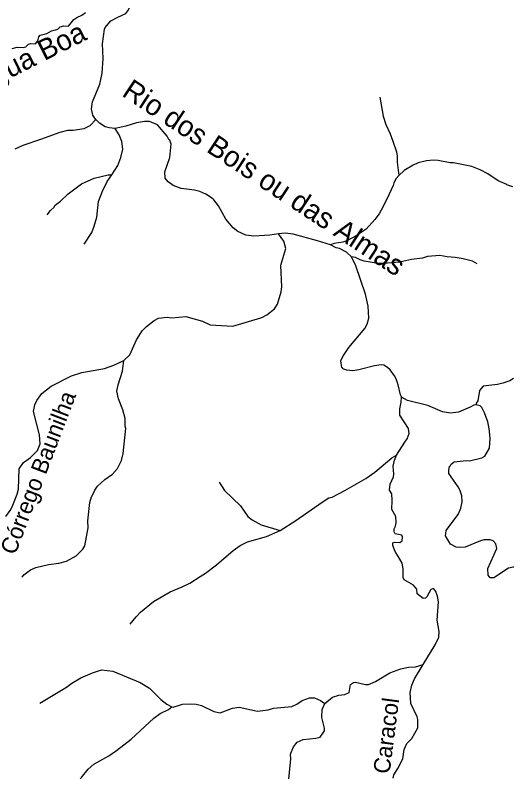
# Model space of a CAD drawing. Extents: x 393 to 446.6, y 8175.5 to 8231.
# Drawn here: x 441.69 to 446.52, y 8219.64 to 8226.96 of the extents above; entities that cross this region are included whole.
import ezdxf
from ezdxf.enums import TextEntityAlignment as Align

# ---------------------------------------------------------------- set-up
doc = ezdxf.new("R2010")
doc.units = 0
doc.header["$LTSCALE"] = 0.064
doc.linetypes.add('LONG_DASHED', pattern=[7.5, 6, -1.5])
doc.layers.add('61', color=7, linetype='Continuous')
doc.layers.add('7', color=7, linetype='Continuous', lineweight=25)
doc.layers.add('9', color=7, linetype='LONG_DASHED', lineweight=25)

msp = doc.modelspace()

# ---------------------------------------------------------------- linework, layer by layer
at = {"layer": '7'}
for points in [[(442.4748, 8225.951), (442.4707, 8225.955), (442.4462, 8225.9931), (442.4316, 8226.0561), (442.4429, 8226.1239), (442.5124, 8226.2951), (442.535, 8226.4017), (442.5463, 8226.5438), (442.5398, 8226.6859), (442.5592, 8226.828), (442.5657, 8226.8441), (442.6205, 8226.907), (442.6868, 8226.9442), (442.7643, 8226.9781), (442.7853, 8227.004), (442.8047, 8227.0411), (442.8047, 8227.054), (442.782, 8227.1267), (442.7078, 8227.2139), (442.5988, 8227.3203)], [(441.6646, 8226.639), (441.7131, 8226.6535), (441.7712, 8226.6487), (441.797, 8226.6551), (441.8228, 8226.681), (441.8455, 8226.6891), (441.8891, 8226.6858), (441.9116, 8226.7133), (441.9213, 8226.7537), (441.9343, 8226.7682), (442.0005, 8226.7843), (442.0457, 8226.8102), (442.0707, 8226.8174), (442.1071, 8226.8279), (442.1281, 8226.8489), (442.1652, 8226.8586), (442.2104, 8226.8554), (442.2605, 8226.9216), (442.2895, 8226.941), (442.3396, 8226.9619), (442.3751, 8226.9878)], [(445.2253, 8226.1685), (445.2591, 8225.985), (445.285, 8225.9027), (445.3254, 8225.8139), (445.3503, 8225.7424), (445.3867, 8225.6378), (445.3948, 8225.5975), (445.3948, 8225.5394), (445.4079, 8225.4097)], [(441.6923, 8225.6685), (441.7696, 8225.7024), (441.9395, 8225.7629), (442.1281, 8225.83), (442.204, 8225.8477), (442.2556, 8225.8477), (442.3622, 8225.8655), (442.4204, 8225.893), (442.4748, 8225.951)], [(442.6606, 8225.8657), (442.6044, 8225.872), (442.5657, 8225.8817), (442.5091, 8225.9172), (442.4748, 8225.951)], [(444.2444, 8224.8438), (444.1611, 8224.832), (444.0061, 8224.8224), (443.9286, 8224.8337), (443.8511, 8224.8692), (443.8058, 8224.9047), (443.7348, 8224.9871), (443.6621, 8225.1163), (443.6169, 8225.1744), (443.5943, 8225.1937), (443.5394, 8225.2309), (443.4829, 8225.2551), (443.4312, 8225.268), (443.302, 8225.2858), (443.2245, 8225.3133), (443.1744, 8225.3504), (443.147, 8225.3827), (443.1438, 8225.4441), (443.1922, 8225.5846), (443.2051, 8225.7138), (443.1922, 8225.7509), (443.1857, 8225.7525), (443.1648, 8225.7913), (443.0727, 8225.8994), (442.9936, 8225.9317), (442.9468, 8225.9317), (442.8693, 8225.9188), (442.7659, 8225.8881), (442.6606, 8225.8657)], [(442.6275, 8225.4182), (442.6867, 8225.5071), (442.7174, 8225.5846), (442.7368, 8225.6653), (442.7255, 8225.7396), (442.6997, 8225.8042), (442.6606, 8225.8657)], [(446.5151, 8225.3016), (446.4561, 8225.3202), (446.4557, 8225.3246), (446.3734, 8225.3585), (446.2732, 8225.4263), (446.199, 8225.4666), (446.1182, 8225.4973), (445.9406, 8225.5312), (445.9083, 8225.5312), (445.792, 8225.5538), (445.7436, 8225.5571), (445.679, 8225.5506), (445.5983, 8225.5312), (445.5498, 8225.5102), (445.4626, 8225.4586), (445.4079, 8225.4097)], [(442.0024, 8225.0309), (442.0344, 8225.0727), (442.0699, 8225.1033), (442.078, 8225.1195), (442.0974, 8225.1372), (442.1313, 8225.1615), (442.2055, 8225.2325), (442.3348, 8225.3294), (442.4591, 8225.3827), (442.5947, 8225.4182), (442.6275, 8225.4182)], [(442.3604, 8224.7441), (442.4365, 8224.8579), (442.4591, 8224.9193), (442.4849, 8225.0065), (442.5011, 8225.1583), (442.5382, 8225.2584), (442.5834, 8225.352), (442.6275, 8225.4182)], [(445.4079, 8225.4097), (445.3851, 8225.3811), (445.3608, 8225.3391), (445.356, 8225.3133), (445.293, 8225.1809), (445.2378, 8225.0753), (445.2187, 8225.0388), (445.1784, 8224.9855), (445.0928, 8224.8918), (444.9975, 8224.8256), (444.9071, 8224.7787), (444.8684, 8224.7658), (444.7844, 8224.7529), (444.749, 8224.7394)], [(444.749, 8224.7394), (444.6226, 8224.7767), (444.3872, 8224.8434), (444.3097, 8224.853), (444.2444, 8224.8438)], [(444.9522, 8224.6239), (444.9023, 8224.6674), (444.836, 8224.7029), (444.8038, 8224.7109), (444.749, 8224.7394)], [(445.4349, 8223.2667), (445.4254, 8223.2878), (445.4045, 8223.382), (445.3851, 8223.4401), (445.369, 8223.4692), (445.327, 8223.5273), (445.3011, 8223.5515), (445.264, 8223.5741), (445.2398, 8223.5774), (445.1752, 8223.5677), (445.0234, 8223.5273), (444.9653, 8223.5192), (444.9071, 8223.5241), (444.8683, 8223.537), (444.8651, 8223.5467), (444.857, 8223.5499), (444.849, 8223.6145), (444.8667, 8223.6565), (444.9249, 8223.7437), (445.0815, 8223.9294), (445.1025, 8223.9698), (445.1186, 8224.0279), (445.1138, 8224.1442), (445.088, 8224.2604), (444.9943, 8224.535), (444.9522, 8224.6239)], [(446.1679, 8224.556), (446.123, 8224.5801), (446.0343, 8224.6043), (445.9567, 8224.6173), (445.8792, 8224.6221), (445.8082, 8224.6366), (445.6887, 8224.627), (445.6386, 8224.6108), (445.5337, 8224.5979), (445.4158, 8224.572), (445.2624, 8224.5591), (445.2107, 8224.5591), (445.0751, 8224.5801), (445.0363, 8224.593), (444.9911, 8224.6173), (444.9522, 8224.6239)], [(446.5196, 8223.444), (446.4841, 8223.4215), (446.4186, 8223.3997), (446.3669, 8223.3868), (446.2264, 8223.3707), (446.1925, 8223.3287), (446.1764, 8223.227), (446.1602, 8223.2043), (446.1577, 8223.1903)], [(446.1577, 8223.1903), (446.1345, 8223.1868), (446.102, 8223.1672), (445.989, 8223.1188), (445.9115, 8223.1074), (445.834, 8223.122), (445.6919, 8223.1833), (445.4949, 8223.2318), (445.4359, 8223.2645), (445.4349, 8223.2667)], [(446.524, 8221.6194), (446.5168, 8221.6177), (446.4734, 8221.6073), (446.3314, 8221.5152), (446.2958, 8221.5136), (446.2765, 8221.5411), (446.2732, 8221.6057), (446.3604, 8221.7995), (446.3507, 8221.8431), (446.3249, 8221.8721), (446.2959, 8221.8818), (446.2345, 8221.8818), (446.2022, 8221.8738), (446.0536, 8221.8108), (445.9955, 8221.8075), (445.9664, 8221.8124), (445.9115, 8221.8414), (445.8631, 8221.9206), (445.8695, 8221.9739), (445.9826, 8222.1257), (445.9864, 8222.1342), (446.0116, 8222.1903), (446.0246, 8222.2516), (446.0213, 8222.3098), (446.0003, 8222.3679), (445.9858, 8222.397), (445.8953, 8222.5261), (445.8937, 8222.5552), (445.9018, 8222.5972), (445.9067, 8222.5972), (445.9164, 8222.6166), (445.947, 8222.6375), (446.0633, 8222.6521), (446.0956, 8222.6488), (446.2151, 8222.6763), (446.2441, 8222.6924), (446.2894, 8222.7716), (446.2958, 8222.8653), (446.2862, 8222.9621), (446.2716, 8223.0235), (446.2409, 8223.1107), (446.2136, 8223.1636), (446.1962, 8223.181), (446.1577, 8223.1903)]]:
    msp.add_lwpolyline(points, dxfattribs=at)
at = {"layer": '9'}
for points in [[(442.7461, 8223.6185), (442.8032, 8223.6751), (442.868, 8223.8203), (442.9229, 8223.9057), (442.9641, 8223.9484), (443.0384, 8224.0064), (443.0802, 8224.0275), (443.1654, 8224.0375), (443.2111, 8224.0327), (443.345, 8224.0458), (443.5062, 8224.0006), (443.5804, 8223.9648), (443.801, 8223.9506), (444.0716, 8224.0323), (444.0823, 8224.0355), (444.1304, 8224.0596), (444.2038, 8224.1206), (444.2348, 8224.1632), (444.2709, 8224.2835), (444.2757, 8224.3309), (444.2661, 8224.5379), (444.266, 8224.5407), (444.3142, 8224.7045), (444.2966, 8224.7754), (444.2444, 8224.8438)], [(441.6005, 8222.1073), (441.6438, 8222.1672), (441.6591, 8222.1965), (441.671, 8222.2192), (441.7121, 8222.3234), (441.7241, 8222.3737), (441.7298, 8222.5705), (441.7741, 8222.6321), (441.8397, 8222.6788), (441.9078, 8222.7474), (441.9341, 8222.8128), (441.9275, 8222.8982), (441.8699, 8223.1252), (441.8828, 8223.1888), (441.9013, 8223.232), (441.951, 8223.3), (442.0398, 8223.3693), (442.2394, 8223.4707), (442.3387, 8223.5012), (442.5595, 8223.542), (442.6489, 8223.5729), (442.7461, 8223.6185)], [(441.76, 8221.5204), (441.7776, 8221.5436), (441.8403, 8221.5928), (441.8933, 8221.615), (442.0148, 8221.6439), (442.116, 8221.6576), (442.1895, 8221.677), (442.2845, 8221.7266), (442.3484, 8221.7919), (442.3684, 8221.8249), (442.4007, 8221.9984), (442.3979, 8222.0679), (442.4172, 8222.2436), (442.4329, 8222.2991), (442.4348, 8222.3032), (442.4632, 8222.3635), (442.4897, 8222.4017), (442.5624, 8222.4676), (442.6345, 8222.5177), (442.6854, 8222.5719), (442.7238, 8222.652), (442.7392, 8222.7192), (442.7641, 8222.962), (442.7578, 8222.984), (442.7576, 8223.0589), (442.7353, 8223.1408), (442.693, 8223.2468), (442.6785, 8223.3222), (442.6899, 8223.3818), (442.7315, 8223.5167), (442.7461, 8223.6185)], [(445.3884, 8222.7027), (445.4688, 8222.8289), (445.4892, 8222.8609), (445.5107, 8222.9116), (445.504, 8222.9612), (445.4192, 8223.0898), (445.4192, 8223.1525), (445.4332, 8223.2166), (445.4349, 8223.2667)], [(444.261, 8221.9734), (444.4129, 8222.0693), (444.6654, 8222.2486), (444.7328, 8222.2878), (444.7641, 8222.2972), (444.8865, 8222.3591), (445.0894, 8222.4765), (445.1774, 8222.5363), (445.3419, 8222.6764), (445.3884, 8222.7027)], [(445.6459, 8220.6753), (445.7612, 8220.866), (445.7967, 8220.9389), (445.8015, 8220.9965), (445.7823, 8221.1036), (445.7951, 8221.2811), (445.7855, 8221.3376), (445.768, 8221.3822), (445.7476, 8221.407), (445.7354, 8221.409), (445.7189, 8221.4006), (445.6822, 8221.3306), (445.6674, 8221.3172), (445.6436, 8221.314), (445.5876, 8221.3611), (445.5837, 8221.4062), (445.5529, 8221.4433), (445.4599, 8221.4944), (445.4523, 8221.5187), (445.4511, 8221.6005), (445.4427, 8221.6559), (445.4053, 8221.7189), (445.3786, 8221.7639), (445.3683, 8221.7871), (445.3498, 8221.8285), (445.3519, 8221.8544), (445.369, 8221.8592), (445.4196, 8221.8551), (445.442, 8221.8744), (445.4456, 8221.9128), (445.4376, 8221.9274), (445.3734, 8221.9404), (445.3639, 8221.9614), (445.3637, 8221.9899), (445.3778, 8222.0135), (445.3848, 8222.0474), (445.3813, 8222.1086), (445.3402, 8222.1768), (445.3463, 8222.2652), (445.3414, 8222.3281), (445.3195, 8222.3639), (445.3253, 8222.4207), (445.359, 8222.493), (445.3623, 8222.5179), (445.353, 8222.5964), (445.3673, 8222.6552), (445.3884, 8222.7027)], [(443.6681, 8222.4397), (443.7197, 8222.3601), (443.8748, 8222.2116), (443.9453, 8222.1082), (443.9891, 8222.0751), (444.0766, 8222.0275), (444.261, 8221.9734)], [(442.8074, 8221.0646), (442.864, 8221.1385), (442.9064, 8221.1808), (443.0332, 8221.2856), (443.1947, 8221.3806), (443.3103, 8221.4267), (443.3836, 8221.4642), (443.4834, 8221.5267), (443.5355, 8221.5594), (443.6435, 8221.6406), (443.8047, 8221.7792), (443.8722, 8221.8269), (443.9434, 8221.8617), (444.1275, 8221.9137), (444.261, 8221.9734)], [(441.9299, 8220.3017), (442.1901, 8220.455), (442.2426, 8220.4945), (442.3285, 8220.5448), (442.4404, 8220.5953), (442.5273, 8220.6252), (442.6402, 8220.6122), (442.9047, 8220.5026), (442.9932, 8220.4464), (443.1046, 8220.3352), (443.1617, 8220.291), (443.21, 8220.2643)], [(444.6924, 8220.2972), (444.6928, 8220.2969), (444.7679, 8220.3603), (444.8287, 8220.3796), (444.885, 8220.3851), (444.9271, 8220.404), (444.9428, 8220.4812), (444.9692, 8220.5027), (444.9884, 8220.5058), (445.0879, 8220.4803), (445.1168, 8220.4804), (445.1827, 8220.5107), (445.3237, 8220.5961), (445.429, 8220.6322), (445.5026, 8220.6486), (445.5723, 8220.6536), (445.6459, 8220.6753)], [(445.3559, 8219.5741), (445.3612, 8219.6064), (445.4013, 8219.6682), (445.4479, 8219.7633), (445.4596, 8219.8526), (445.4861, 8219.9102), (445.5366, 8219.9585), (445.5932, 8220.0612), (445.5935, 8220.142), (445.5865, 8220.169), (445.5257, 8220.2992), (445.518, 8220.4046), (445.5352, 8220.4753), (445.5611, 8220.5351), (445.6459, 8220.6753)], [(443.21, 8220.2643), (443.2238, 8220.2628), (443.3123, 8220.2912), (443.3956, 8220.296), (443.4473, 8220.2911), (443.4977, 8220.2769), (443.6157, 8220.2191), (443.6777, 8220.2075), (443.7994, 8220.2524), (443.8637, 8220.2621), (444.0409, 8220.2236), (444.1437, 8220.2377), (444.194, 8220.254), (444.3735, 8220.2685), (444.4217, 8220.2901), (444.4742, 8220.3266), (444.5434, 8220.3525), (444.5797, 8220.3519), (444.594, 8220.3517), (444.6493, 8220.328), (444.6924, 8220.2972)], [(442.195, 8219.2404), (442.3038, 8219.5252), (442.3331, 8219.5774), (442.3997, 8219.6635), (442.4531, 8219.7117), (442.6, 8219.79), (442.6746, 8219.8412), (442.8161, 8219.9539), (443.036, 8220.1562), (443.0975, 8220.1999), (443.1775, 8220.2402), (443.21, 8220.2643)], [(444.0027, 8219.2705), (444.0095, 8219.3125), (444.0473, 8219.353), (444.1124, 8219.3623), (444.1514, 8219.3466), (444.1961, 8219.345), (444.2089, 8219.3562), (444.2486, 8219.3623), (444.3081, 8219.4393), (444.3263, 8219.4789), (444.3418, 8219.5355), (444.3626, 8219.7583), (444.3613, 8219.807), (444.3887, 8219.8776), (444.4244, 8219.9229), (444.4833, 8219.9489), (444.6054, 8219.9616), (444.6483, 8219.9717), (444.6892, 8220.0323), (444.6898, 8220.0597), (444.6631, 8220.1635), (444.6678, 8220.2401), (444.6924, 8220.2971), (444.6924, 8220.2972)]]:
    msp.add_lwpolyline(points, dxfattribs=at)

# ---------------------------------------------------------------- texts
at = {"layer": '61'}
for s, height, rotation, p in [('Córr. Água Boa', 0.2, 26.727, (441.5767, 8226.3164)), ('Rio dos Bois ou das Almas', 0.2, 326.584, (444.0504, 8225.3074)), ('Córrego Baunilha', 0.16, 69.146, (441.9887, 8222.5058)), ('Córrego Caracol', 0.16, 82.6, (445.3129, 8219.5634))]:
    msp.add_text(s, height=height, rotation=rotation, dxfattribs=at).set_placement(p, align=Align.CENTER)

doc.saveas('drawing.dxf')
